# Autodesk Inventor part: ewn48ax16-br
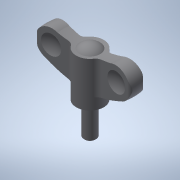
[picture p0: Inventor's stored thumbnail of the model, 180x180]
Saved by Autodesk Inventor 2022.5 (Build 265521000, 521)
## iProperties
Created: 2017-05
Part Number: ewn48ax16-br
Material: 一般
Document SubType Name: Modeling
Designer: imaocorp
Density: 1 g/cm^3
Appearance: 既定
Author: imaocorp
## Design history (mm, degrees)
node "ewn48ax16-br.x_t1"
node "ewn48ax16-br"
node "Base1"
